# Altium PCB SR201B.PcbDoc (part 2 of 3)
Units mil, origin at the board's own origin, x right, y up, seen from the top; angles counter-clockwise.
Board outline 4100 x 3600 mil, 4 copper layers (Top Layer, Signal Layer 1, Signal Layer 2, Bottom Layer), stack 61.6 mil thick; 173 components, 61 nets, 385 pads, 260 vias.
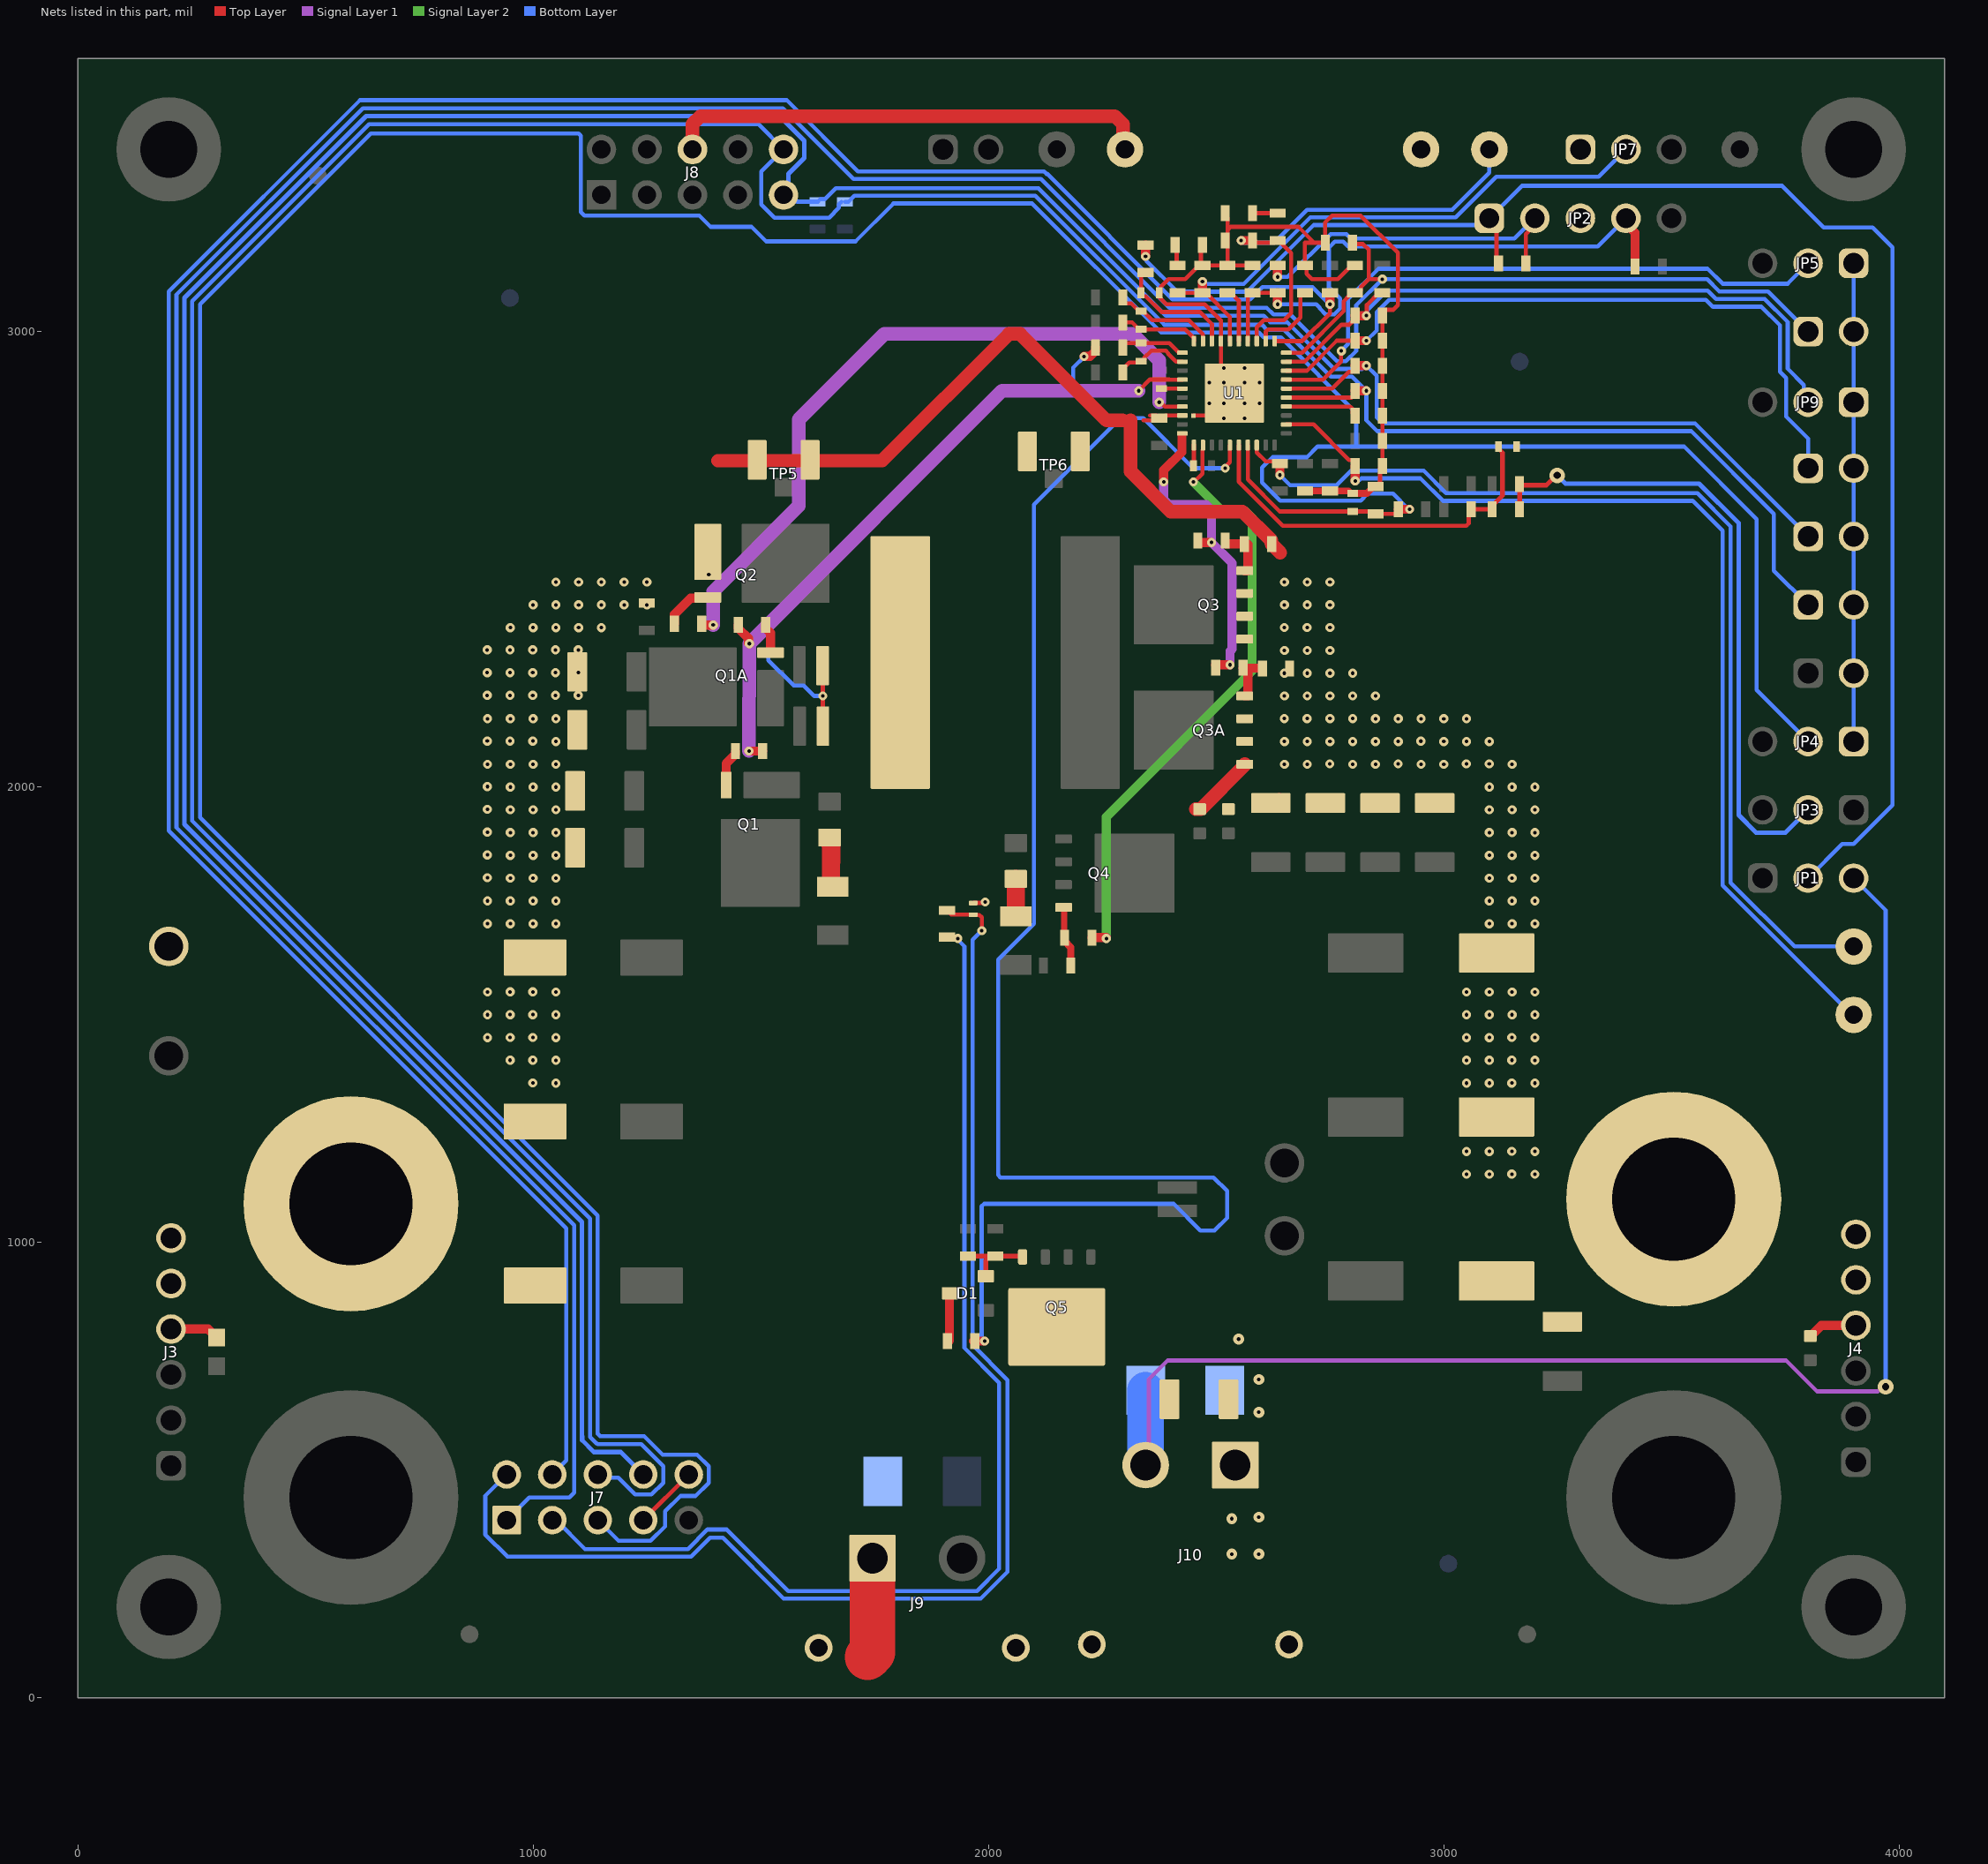
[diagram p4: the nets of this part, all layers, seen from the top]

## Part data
C1 C2 C12 C28: library part CMP-0007099-4, "CAP, CERM, 0.1 uF, 100 V, +/- 10%, X7S, AEC-Q200 Grade 1, 0603", Cap_Case=0603, Manufacturer=TDK, Supplier Part Number 1=445-6938-1-ND, TempCo=X7S, Tolerance_%=10%, Value1="0.04959 ohm", Value2=100V, ValueDisplayed=0.1uF
C3 C5 C6 C9 C14 C20 C21 C22 C40: library part CMP-0125410-1, "10 µF ±10% 100V Ceramic Capacitor X7R 1210 (3225 Metric)", Digikey Part Number=445-CGA6P1X7R2A106K250ACCT-ND, Manufacturer=TDK, Mouser Part Number=810-CGA6P1X7R2A106K2, Operating Temperature Range="-55°C to +125°C", TempCo=15%, Temperature Characteristic=X7R, Tolerance_%=10%, ValueDisplayed=10uF
C4 C7 C23: library part CMP-0097690-1, "Cap Aluminum Polymer 27uF 63V 20% Solder Cylindrical 54m Ohm 1175mA 2000 hr 125°C T/R", Digikey Part Number=399-A768KE276M1JLAE054CT-ND, Leakage Current=340uA, Manufacturer=KEMET, Mouser Part Number=80-A768KE276M1JLAE54, Operating Temperature Range="-55°C to +125°C", Tolerance_%=20%, ValueDisplayed=27uF
C8 C10 C13: library part CMP-0088837-1, "0.1µF ±10% 100V Ceramic Capacitor X7R 0603 (1608 Metric)", Digikey Part Number=490-3285-1-ND, Manufacturer=Murata, Mouser Part Number=81-GRM188R72A104KA35, Operating Temperature Range="-55°C to +125°C", TempCo=15%, Temperature Characteristic=X7R, Tolerance_%=10%, ValueDisplayed=0.1uF
C11: library part CMP-0064935-4, "CAP, CERM, 0.1 uF, 100 V,+/- 10%, X7R, AEC-Q200 Grade 1, 0603", Cap_Case=0603, Manufacturer=MuRata, Supplier Part Number 1=490-13420-1-ND, TempCo=X7R, Tolerance_%=10%, Value1=Unknown, Value2=100V, ValueDisplayed=0.1uF
C15 C16 C29: library part CMP-0006618-2, "CAP, CERM, 0.1 uF, 100 V, +/- 10%, X5R, 0402", Cap_Case=0402, Manufacturer=MuRata, Supplier Part Number 1=490-10458-1-ND, TempCo=X5R, Tolerance_%=10%, Value1=Unknown, Value2=100V, ValueDisplayed=0.1uF
C17 C18 C19: library part CMP-0128071-1, "27 µF 80 V Aluminum - Polymer Capacitors Radial, Can - SMD 38mOhm 4000 Hrs @ 125°C", Digikey Part Number=493-13785-1-ND, Leakage Current=64uA, Manufacturer=Nichicon, Mouser Part Number=647-PCR1K270MCL1GS, Operating Temperature Range="-55°C to +125°C", Tolerance_%=20%, ValueDisplayed=27uF
C24: library part CMP-0006675-2, "CAP, CERM, 0.1 uF, 50 V, +/- 20%, X7R, 0402", Cap_Case=0402, Manufacturer=MuRata, Supplier Part Number 1=490-10701-1-ND, TempCo=X7R, Tolerance_%=20%, Value1=Unknown, Value2=50V, ValueDisplayed=0.1uF
C25: library part CMP-0006445-2, "CAP, CERM, 270 pF, 50 V, +/- 5%, C0G/NP0, 0402", Cap_Case=0402, Manufacturer=MuRata, Supplier Part Number 1=490-1294-1-ND, TempCo=C0G/NP0, Tolerance_%=5%, Value1=Unknown, Value2=50V, ValueDisplayed=270pF
C26 C27: library part CMP-0092433-2, "Multi-Layer Ceramic Capacitor 22uF 10V X5R ±20% 0603 Paper T/R", Manufacturer=Murata, Operating Temperature Range="-55°C to +85°C", TempCo=15%, Temperature Characteristic=X5R, Tolerance_%=20%, ValueDisplayed=22uF
C30: library part CMP-0007537-2, "CAP, CERM, 680 pF, 100 V, +/- 5%, C0G/NP0, 0805", Cap_Case=0805, Manufacturer=AVX, Supplier Part Number 1=478-1289-1-ND, TempCo=C0G/NP0, Tolerance_%=5%, Value1="0.134 ohm", Value2=100V, ValueDisplayed=680pF
C31 C33: library part CMP-0006356-2, "CAP, CERM, 0.1 uF, 50 V, +/- 10%, X7R, AEC-Q200 Grade 1, 0402", Cap_Case=0402, Manufacturer=MuRata, Supplier Part Number 1=490-10672-1-ND, TempCo=X7R, Tolerance_%=10%, Value1=Unknown, Value2=50V, ValueDisplayed=0.1uF
C32: library part CMP-0007709-2, "CAP, CERM, 1000 pF, 100 V, +/- 5%, C0G/NP0, 0805", Cap_Case=0805, Manufacturer=Kemet, Supplier Part Number 1=399-1137-1-ND, TempCo=C0G/NP0, Tolerance_%=5%, Value1="0.025 ohm", Value2=100V, ValueDisplayed=1000pF
C34: library part CMP-0006776-4, "CAP, CERM, 220 pF, 50 V, +/- 1%, C0G/NP0, 0603", Cap_Case=0603, Manufacturer=AVX, Supplier Part Number 1=478-3719-1-ND, TempCo=C0G/NP0, Tolerance_%=1%, Value1="0.083 ohm", Value2=50V, ValueDisplayed=220pF
C35: library part CMP-0006792-4, "CAP, CERM, 56 pF, 50 V, +/- 1%, C0G/NP0, 0603", Cap_Case=0603, Manufacturer=AVX, Supplier Part Number 1=478-7922-1-ND, TempCo=C0G/NP0, Tolerance_%=1%, Value1=Unknown, Value2=50V, ValueDisplayed=56pF
C36: library part CMP-0084236-1, "CAP, CERM, 0.012 µF, 50 V,+/- 10%, X7R, AEC-Q200 Grade 1, 0603", Cap_Case=0603, Manufacturer=Kemet, TempCo=X7R, Tolerance_%=10%, Value2=50V, ValueDisplayed=0.012µF
C37: library part CMP-0086295-1, "CAP, CERM, 0.02 µF, 50 V,+/- 10%, X7R, 0603", Cap_Case=0603, Manufacturer=Yageo, TempCo=X7R, Tolerance_%=10%, Value2=50V, ValueDisplayed=0.02µF
C38: library part CMP-0006745-4, "CAP, CERM, 4700 pF, 100 V, +/- 5%, X7R, 0603", Cap_Case=0603, Manufacturer=AVX, Supplier Part Number 1=478-3710-1-ND, TempCo=X7R, Tolerance_%=5%, Value1="0.136 ohm", Value2=100V, ValueDisplayed=4700pF
C39: library part CMP-0085252-1, "CAP, CERM, 0.047 µF, 50 V,+/- 5%, X7R, 0603", Cap_Case=0603, Manufacturer=AVX, TempCo=X7R, Tolerance_%=5%, Value2=50V, ValueDisplayed=0.047µF
C41: library part CMP-0096021-1, "10 µF ±10% 100V Ceramic Capacitor X7R 1210 (3225 Metric)", Digikey Part Number=445-C3225X7R2A106K250ACCT-ND, Manufacturer=TDK, Mouser Part Number=810-C3225X7R2A106K25, Operating Temperature Range="-55°C to +125°C", TempCo=15%, Temperature Characteristic=X7R, Tolerance_%=10%, ValueDisplayed=10uF
C42: library part CMP-0006943-4, "CAP, CERM, 4700 pF, 50 V, +/- 10%, X7R, 0603", Cap_Case=0603, Manufacturer=Kemet, Supplier Part Number 1=399-1087-1-ND, TempCo=X7R, Tolerance_%=10%, Value1=Unknown, Value2=50V, ValueDisplayed=4700pF
C43 C44: library part CMP-0006959-4, "CAP, CERM, 680 pF, 50 V, +/- 5%, C0G/NP0, 0603", Cap_Case=0603, Manufacturer=Kemet, Supplier Part Number 1=399-3289-1-ND, TempCo=C0G/NP0, Tolerance_%=5%, Value1=Unknown, Value2=50V, ValueDisplayed=680pF
D1: library part CMP-0096356-1, "Diode Array 1 Pair Series Connection Schottky 70 V 200mA (DC) Surface Mount TO-236-3, SC-59, SOT-23-3", Digikey Part Number=BAS70-04-E3-18GICT-ND, Forward Current=200mA, Manufacturer=Vishay, Max Surge Forward Current=600mA, Mouser Part Number=78-BAS70-04-E3-18, Operating Temperature Range="-55°C to +125°C", Peak Reverse Current=0.02uA, ValueDisplayed=1.5pF
D2 D3: library part CMP-0005570-3, "Diode, TVS, Uni, 48 V, 77.4 Vc, SMB", Manufacturer="Diodes Inc.", Value1=600W
FID1 FID2 FID3 FID4 FID5 FID6: library part CMP-0077181-1, "Fiducial mark.  There is nothing to buy or mount.", Manufacturer=N/A
H1 H2 H3 H4: library part CMP-0003715-1, "MACHINE SCREW PAN PHILLIPS 4-40", Manufacturer="B&F Fastener Supply", Supplier Part Number 1=H703-ND
J1 J2 J5 J6: library part CMP-0055387-2, "Standard Banana Jack, Uninsulated, 15A", Manufacturer="Cinch Connectivity", Supplier Part Number 1=J147-ND
J3 J4: library part CMP-0054801-2, "Header, 2.54 mm, 6x1, Gold, TH", Color=Black, Manufacturer="Wurth Elektronik", Supplier Part Number 1=732-5319-ND
J7: library part CMP-0120964-1, "10 Position Receptacle Connector 0.100\" (2.54mm) Through Hole, Right Angle Gold", Current_A=4.7A, Digikey Part Number=SAM1215-05-ND, Manufacturer=Samtec, Mouser Part Number=200-SSW10502GDRA, Operating Temperature Range="-55°C to +125°C", Voltage_V=655V
J8: library part CMP-0055448-2, "Header (shrouded), 100mil, 5x2, High-Temperature, Gold, TH", Manufacturer=3M, Supplier Part Number 1=MHC10K-ND
J9: library part CMP-0035193-3, "Socket, DC supply, XT30, female, PIN: 2, on PCBs, THT, yellow, 15A", Current_A=15A, Manufacturer=Amass, Operating Temperature Range="-20°C to +120°C", Voltage_V=500V
J10: library part CMP-0121007-1, "Socket, DC supply, XT30, male, PIN: 2, on PCBs, THT, yellow, 15A, 500V", Current_A=15A, Manufacturer=Amass, Operating Temperature Range="-20°C to +120°C", Voltage_V=500V
J11 JP6 JP8 JP10 JP11 JP12 JP13: library part CMP-0054794-2, "Header, 2.54 mm, 2x1, Gold, TH", Color=Black, Manufacturer="Wurth Elektronik", Supplier Part Number 1=732-5315-ND
JP1 JP3 JP4 JP5 JP7 JP9: library part CMP-0054796-4, "Header, 2.54 mm, 3x1, Gold, TH", Manufacturer="Wurth Elektronik", Supplier Part Number 1=732-5316-ND
JP2: library part CMP-0084909-1, "Header, 2.54mm, 5x1, Gold, TH", Color=Black, Current_A=3A, Manufacturer="Wurth Elektronik", Voltage_V=250V
L1: library part CMP-0084625-1, "Inductor, Shielded, Metal Composite, 4.7 µH, 17 A, 0.00385 ohm, SMD", Manufacturer="Wurth Elektronik", Value1="0.00385 ohm", Value2=17A, ValueDisplayed=4.7µH
Logo3: library part CMP-0074847-1, "FCC_disclaimer"
LOGO4: library part CMP-0074769-4, Manufacturer="Texas Instruments"
Logo5: library part CMP-0074837-2, "IEC 61010-1 Hot Surface Warning", Manufacturer="Texas Instruments"
Logo6: library part CMP-0074836-1, "IEC 61010-1 Caution Warning"
LOGO7: library part CMP-0074835-1, "IEC 61010-1 High Voltage Warning"
MP1 MP2 MP3 MP4: library part CMP-0090542-1, "Hex Standoff Threaded #4-40 Nylon 0.750\" (19.05mm) 3/4\" Natural", Digikey Part Number=36-1902D-ND, Manufacturer="Keystone Electronics", Mouser Part Number=534-1902D, Operating Temperature Range=to
NT3: library part CMP-0078142-6, "Single point connection between nets.", Manufacturer=N/A
Q1 Q1A Q2: library part CMP-0128065-1, "MOSFET N-Channel 80 V 130A (Tj) 118W (Tc) Surface Mount PG-TDSON-8-34", Digikey Part Number=448-IAUCN08S7L033ATMA1CT-ND, Drain To Source Breakdown Voltage=80V, Input Capacitance At Vds="2708pF @ 40V", Manufacturer=Infineon, Mouser Part Number=726-IAUCN08S7L033ATM, Operating Temperature Range="-55°C to +175°C", Power_W=118W, Pulse Drain Current=356A, Typ Forward Diode Voltage=0.9V
Q3 Q3A Q4: library part CMP-0097724-1, "MOSFET N-Channel 60 V 23A (Ta), 135A (Tc) 3W (Ta), 100W (Tc) Surface Mount PG-TDSON-8", Digikey Part Number=448-ISC0703NLSATMA1CT-ND, Drain To Source Breakdown Voltage=60V, Input Capacitace At Vds="2700pF @ 30V", Manufacturer=Infineon, Mouser Part Number=726-ISC0703NLSATMA1, Operating Temperature Range="-55°C to +175°C", Power_W=3W, Pulse Drain Current=540A, Typ Forward Diode Voltage=0.85V
Q5: library part CMP-0000823-2, "MOSFET, N-CH, 60 V, 100 A, DNK0008A (VSON-CLIP-8)", Alternate Manufacturer=None, Manufacturer="Texas Instruments", Supplier Part Number 1=296-41076-1-ND, Value1=0.003, Value2="41 nC"
R1: library part CMP-0023198-5, "RES, 5.10 k, 1%, 0.1 W, 0603", Manufacturer=Yageo, Power_W=100mW, Supplier Part Number 1=311-5.10KHRCT-ND, TempCo="100 ppm/C", Tolerance_%=1%, Value2=0.1W, Value_Code=5k10, ValueDisplayed=5.10k
R2 R5 R7 R9 R10 R11 R15 R16 R20 R24 R27 R36 R38 R44: library part CMP-0023343-3, "RES, 0, 1%, 0.1 W, AEC-Q200 Grade 0, 0603", Manufacturer="Stackpole Electronics Inc", Power_W=100mW, Supplier Part Number 1=RMCF0603ZT0R00CT-ND, TempCo=ppm/C, Tolerance_%=1%, Value2=0.1W, Value_Code=0
R3: library part CMP-0097451-1, "10 mOhms ±1% 1W Chip Resistor Wide 0805 (2012 Metric), 0508 Automotive AEC-Q200, Current Sense Metal Foil", Manufacturer=Susumu, Operating Temperature Range="-55°C to +155°C", Power_W=1W, TempCo=50ppm/°C, Tolerance_%=1%
R4 R6: library part CMP-0090651-1, "5 mOhms ±1% 1W Chip Resistor Wide 0805 (2012 Metric), 0508 Automotive AEC-Q200, Current Sense Metal Foil", Digikey Part Number=408-1595-1-ND, Manufacturer=Susumu, Mouser Part Number=754-KRL2012EMR005FT5, Operating Temperature Range="-55°C to +155°C", Power_W=1W, TempCo=50ppm/°C, Tolerance_%=1%
R8: library part CMP-0022751-4, "RES, 10.0, 1%, 0.1 W, 0603", Manufacturer=Yageo, Power_W=100mW, Supplier Part Number 1=311-10.0HRCT-ND, TempCo="100 ppm/C", Tolerance_%=1%, Value2=0.1W, Value_Code=10R0, ValueDisplayed=10.0
R12: library part CMP-0023292-5, "RES, 82.0 k, 1%, 0.1 W, 0603", Manufacturer=Yageo, Power_W=100mW, Supplier Part Number 1=311-82.0KHRCT-ND, TempCo="100 ppm/C", Tolerance_%=1%, Value2=0.1W, Value_Code=82k0, ValueDisplayed=82.0k
R13 R14 R28: library part CMP-0025804-4, "RES, 3.0, 5%, 0.1 W, AEC-Q200 Grade 0, 0603", Manufacturer=Vishay-Dale, Power_W=100mW, Supplier Part Number 1=541-3.0GCT-ND, TempCo="200 ppm/C", Tolerance_%=5%, Value2=0.1W, Value_Code=3R00, ValueDisplayed=3.0
R17 R18: library part CMP-0022004-4, "RES, 10.0, 1%, 0.25 W, AEC-Q200 Grade 0, 0603", Manufacturer=Vishay-Dale, Power_W=250mW, Supplier Part Number 1=541-10.0SCT-ND, TempCo="100 ppm/C", Tolerance_%=1%, Value2=0.25W, Value_Code=10R0, ValueDisplayed=10.0
R19: library part CMP-0023148-5, "RES, 4.30 k, 1%, 0.1 W, 0603", Manufacturer=Yageo, Power_W=100mW, Supplier Part Number 1=311-4.30KHRCT-ND, TempCo="100 ppm/C", Tolerance_%=1%, Value2=0.1W, Value_Code=4k30, ValueDisplayed=4.30k
R21: library part CMP-0023267-5, "RES, 75.0 k, 1%, 0.1 W, 0603", Manufacturer=Yageo, Power_W=100mW, Supplier Part Number 1=311-75.0KHRCT-ND, TempCo="100 ppm/C", Tolerance_%=1%, Value2=0.1W, Value_Code=75k0, ValueDisplayed=75.0k
R22: library part CMP-0022778-5, "RES, 12.7 k, 1%, 0.1 W, 0603", Manufacturer=Yageo, Power_W=100mW, Supplier Part Number 1=311-12.7KHRCT-ND, TempCo="100 ppm/C", Tolerance_%=1%, Value2=0.1W, Value_Code=12k7, ValueDisplayed=12.7k
R23 R26: library part CMP-0018676-3, "RES, 3.0, 5%, 0.25 W, AEC-Q200 Grade 0, 1206", Manufacturer=Vishay-Dale, Power_W=250mW, Supplier Part Number 1=541-3.0ECT-ND, TempCo="200 ppm/C", Tolerance_%=5%, Value2=0.25W, Value_Code=3R00, ValueDisplayed=3.0
R25: library part CMP-0023653-3, "RES, 10.0 k, 0.1%, 0.1 W, 0603", Manufacturer="Yageo America", Power_W=100mW, TempCo="25 ppm/C", Tolerance_%=0.1%, Value2=0.1W, Value_Code=10k0, ValueDisplayed=10.0k
R29: library part CMP-0022599-4, "RES, 7.15 k, 1%, 0.1 W, AEC-Q200 Grade 0, 0603", Manufacturer=Vishay-Dale, Power_W=100mW, Supplier Part Number 1=541-7.15KHCT-ND, TempCo="100 ppm/C", Tolerance_%=1%, Value2=0.1W, Value_Code=7k15, ValueDisplayed=7.15k
R30: library part CMP-0022410-4, "RES, 40.2 k, 1%, 0.1 W, AEC-Q200 Grade 0, 0603", Manufacturer=Vishay-Dale, Power_W=100mW, Supplier Part Number 1=541-40.2KHCT-ND, TempCo="100 ppm/C", Tolerance_%=1%, Value2=0.1W, Value_Code=40k2, ValueDisplayed=40.2k
R31: library part CMP-0023330-5, "RES, 97.6 k, 1%, 0.1 W, 0603", Manufacturer=Yageo, Power_W=100mW, Supplier Part Number 1=311-97.6KHRCT-ND, TempCo="100 ppm/C", Tolerance_%=1%, Value2=0.1W, Value_Code=97k6, ValueDisplayed=97.6k
R32 R33: library part CMP-0025807-4, "RES, 3.9, 5%, 0.1 W, AEC-Q200 Grade 0, 0603", Manufacturer=Vishay-Dale, Power_W=100mW, Supplier Part Number 1=541-3.9GCT-ND, TempCo="200 ppm/C", Tolerance_%=5%, Value2=0.1W, Value_Code=3R90, ValueDisplayed=3.9
R34: library part CMP-0022204-4, "RES, 20.0 k, 1%, 0.1 W, AEC-Q200 Grade 0, 0603", Manufacturer=Vishay-Dale, Power_W=100mW, Supplier Part Number 1=541-20.0KHCT-ND, TempCo="100 ppm/C", Tolerance_%=1%, Value2=0.1W, Value_Code=20k0, ValueDisplayed=20.0k
R35: library part CMP-0023068-4, "RES, 390 k, 1%, 0.1 W, 0603", Manufacturer=Yageo, Power_W=100mW, Supplier Part Number 1=311-390KHRCT-ND, TempCo="100 ppm/C", Tolerance_%=1%, Value2=0.1W, Value_Code=390k
R37: library part CMP-0022205-4, "RES, 20.5 k, 1%, 0.1 W, AEC-Q200 Grade 0, 0603", Manufacturer=Vishay-Dale, Power_W=100mW, Supplier Part Number 1=541-20.5KHCT-ND, TempCo="100 ppm/C", Tolerance_%=1%, Value2=0.1W, Value_Code=20k5, ValueDisplayed=20.5k
R39 R40: library part CMP-0023000-5, "RES, 2.00 k, 1%, 0.1 W, 0603", Manufacturer=Yageo, Power_W=100mW, Supplier Part Number 1=311-2.00KHRCT-ND, TempCo="100 ppm/C", Tolerance_%=1%, Value2=0.1W, Value_Code=2k00, ValueDisplayed=2.00k
R41: library part CMP-0022381-4, "RES, 3.83 k, 1%, 0.1 W, AEC-Q200 Grade 0, 0603", Manufacturer=Vishay-Dale, Power_W=100mW, Supplier Part Number 1=541-3.83KHCT-ND, TempCo="100 ppm/C", Tolerance_%=1%, Value2=0.1W, Value_Code=3k83, ValueDisplayed=3.83k
R42: library part CMP-0023307-5, "RES, 8.25 k, 1%, 0.1 W, 0603", Manufacturer=Yageo, Power_W=100mW, Supplier Part Number 1=311-8.25KHRCT-ND, TempCo="100 ppm/C", Tolerance_%=1%, Value2=0.1W, Value_Code=8k25, ValueDisplayed=8.25k
R43: library part CMP-0025686-1, "RES, 10.0 k, 0.1%, 0.1 W, AEC-Q200 Grade 1, 0603", Manufacturer=Vishay-Dale, Power_W=100mW, Supplier Part Number 1=TNP10.0KAACT-ND, TempCo="25 ppm/C", Tolerance_%=0.1%, Value2=0.1W, Value_Code=10k0, ValueDisplayed=10.0k
RT1: library part CMP-0123214-2, "±1% tolerance 10kΩ linear thermistor available in 0402 and 0603 package options 2-X1SON -40 to 125", Digikey Part Number=296-TMP6131DECRCT-ND, Manufacturer="Texas Instruments", Mouser Part Number=595-TMP6131DECR, Operating Temperature Range="-40°C to +125°C", Tolerance_%=1%
SH-JP1 SH-JP2 SH-JP3 SH-JP4 SH-JP5 SH-JP6 SH-JP7 SH-JP8 SH-JP9 SH-JP10 SH-JP11 SH-JP12: library part CMP-0078738-1, "Single Operation 2.54mm Pitch Open Top Jumper Socket", Manufacturer=Harwin, Supplier Part Number 1=952-2881-ND
TP1 TP2: library part CMP-0055150-2, "Test Point, Multipurpose, Orange, TH", Color=Orange, Manufacturer="Keystone Electronics", Supplier Part Number 1=36-5013-ND
TP3: library part CMP-0055147-2, "Test Point, Multipurpose, Red, TH", Color=Red, Manufacturer="Keystone Electronics", Supplier Part Number 1=36-5010-ND
TP4 TP7: library part CMP-0055138-2, "Test Point, Miniature, Black, TH", Color=Black, Manufacturer="Keystone Electronics", Supplier Part Number 1=36-5001-ND
TP5 TP6: library part CMP-0124001-1, "U.FL (UMCC), I-PEX MHFI Connector Receptacle, Male Pin 50 Ohms Surface Mount Solder", Dielectric Material="Liquid Crystal Polymer", Digikey Part Number=SAM10680-ND, Frequency_Fixed=6GHz, Manufacturer=Samtec, Operating Temperature Range="-40°C to +90°C", Voltage_V=60V
TP8: library part CMP-0055148-2, "Test Point, Multipurpose, Black, TH", Color=Black, Manufacturer="Keystone Electronics", Supplier Part Number 1=36-5011-ND
TP9 TP10 TP11 TP12 TP13: library part CMP-0055141-2, "Test Point, Miniature, Yellow, TH", Color=Yellow, Manufacturer="Keystone Electronics", Supplier Part Number 1=36-5004-ND
U1: library part CMP-0127274-2, "80V VIN4 Switch Buck-Boost Controller with I2C", Manufacturer="Texas Instruments", Operating Temperature Range=to
ZZ2: library part CMP-0077236-1
ZZ3: library part CMP-0077237-1
ZZ4: library part CMP-0077238-1

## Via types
v1: diameter 20, hole 8, Top Layer to Bottom Layer, tented both sides, 239 vias
v2: diameter 19.68, hole 7.87, Top Layer to Bottom Layer, tented both sides, 12 vias
v3: diameter 24, hole 8, Top Layer to Bottom Layer, tented both sides, 7 vias
v4: diameter 34, hole 16, Top Layer to Bottom Layer, tented both sides, 2 vias

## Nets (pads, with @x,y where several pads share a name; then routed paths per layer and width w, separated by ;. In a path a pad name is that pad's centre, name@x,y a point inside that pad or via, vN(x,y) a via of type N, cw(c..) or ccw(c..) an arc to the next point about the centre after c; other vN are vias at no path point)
ADDR: JP9.2 R36.2 R38.1 U1.9 | length 1467.9
  Top Layer w9: U1.9@2654.17,2933.9 2654.59,2934.32 2694.32,2934.32 2775,3015 2792.5,3015 2805,3027.5 R38.1@2805,3035 ; v1(2830,3035) 2831,3036 2831,3058.5 2857.5,3085 R36.2@2865,3085
  Top Layer w20: R38.1@2805,3035 v1(2830,3035)
  Bottom Layer w9: v1(2830,3035) 2832.1,3037.1 2832.1,3047.1 2875,3090 3579.49,3090 3598.09,3071.4 3704.74,3071.4 3755.15,3020.99 3755.15,2918.48 3790.8,2882.83 3790.8,2854.2 JP9.2@3800,2845
AGND: C15.1 C16.2 C26.1 C28.1 C29.2 C34.2 C35.2 C36.2 C37.2 C38.2 C39.2 J8.6 J11.2 JP2.3 JP4.1 JP5.1 JP6.2 JP7.1 JP8.2 JP9.1 JP10.2 JP11.2 JP13.1 NT3.2 R10.1 R19.1 R22.1 R24.1 R27.1 R30.1 R31.1 R37.1 R38.2 R41.1 R42.1 TP4.1 TP7.1 U1.17 U1.41 | length 4306
  Top Layer w9: NT3.2@2450.26,2815.5 2490.5,2815.5 v2(2517.36,2842.36) U1.41@2540,2865 ; C39.2@2466.57,3190 2466.57,3148.43 C38.2@2470,3145 ; v2(2517.36,2920.12) 2515.82,2920.12 2510.47,2925.46 U1.17@2510.47,2979.17 2510.47,3024.53 2475,3060 2390.5,3060 2372.5,3078 2378,3083.5 2378,3097.69 2395.32,3115 2432.5,3115 2462.5,3145 2466.57,3145 C38.2@2470,3145 ; C36.2@2525,3250 2525,3222.5 ; R19.1@2580,3145 R10.1@2525,3145 ; R30.1@2805,3145 2797.5,3145 2767.5,3115 2710.56,3115 2698.79,3126.77 2698.79,3141.21 R31.1@2695,3145 2695,3195 2715.67,3195 ; R22.1@2850,2660 R22.1@2854.5,2664.5 ; R22.1@2860,2664.5 R22.1@2854.5,2664.5 ; R22.1@2860,2665.5 R22.1@2860,2668.31 ; C38.2@2470,3145 R10.1@2525,3145 ; R10.1@2525,3145 2525,3195 2525,3222.5 ; 2525,3222.5 2532.5,3230 2680.67,3230 2715.67,3195 ; 2715.67,3195 C35.2@2739.68,3195 2739.68,3239.68 2755,3255 2817.21,3255 2899.07,3173.14 2899.07,3057.71 2889.37,3048 2870.5,3048 2865,3042.5 R38.2@2865,3035 R37.1@2865,2980 R42.1@2865,2925 R41.1@2865,2870 R27.1@2865,2815 R24.1@2865,2760 C37.2@2865,2705 2860,2700 R22.1@2860,2668.31 ; R22.1@2854.5,2664.5 2858.31,2668.31 R22.1@2860,2668.31
  Top Layer w15: C28.1@2695,2650 C26.1@2750,2650 2790.5,2650 2795.5,2645 2831.21,2645 2840,2653.79 2840,2657.5 2842.5,2660 R22.1@2850,2660
  Top Layer w30: J8.6@1350,3400 1350,3455.44 1367.57,3473.01 2277.65,3473.01 2295.23,3455.44 2295.23,3404.77 TP7.1@2300,3400
  Bottom Layer w9: JP13.1@3900,2100 JP6.2@3900,2250 JP10.2@3900,2400 JP11.2@3900,2550 JP8.2@3900,2700 JP9.1@3900,2845 J11.2@3900,3000 JP5.1@3900,3150
  other v2: 2517.36,2809.88 2562.64,2809.88 2484.88,2842.36 2562.64,2842.36 2595.12,2842.36 2484.88,2887.64 2517.36,2887.64 2562.64,2887.64 2595.12,2887.64 2562.64,2920.12
BIAS: JP3.2 R5.2 R11.2 | length 1416
  Top Layer w10: R5.2@3166.69,2609.65 3166.69,2662.17 3167.19,2662.66 3225.38,2662.66 3247.12,2684.4 v4(3248.9,2684.4)
  Bottom Layer w10: v4(3248.9,2684.4) 3267.25,2666.05 3560.63,2666.05 3647.37,2579.31 3647.37,1938.49 3685.86,1900 3750,1900 JP3.2@3800,1950
BIAS36: C15.2 R5.1 R7.1 U1.36 | length 861.3
  Top Layer w9: U1.36@2549.84,2750.83 2549.84,2670.16 2646.32,2573.68 3049.46,2573.68 3054.73,2578.96 3054.73,2610 R7.1@3060,2610
  Top Layer w10: R7.1@3060,2610 3060.35,2609.65 R5.1@3106,2609.65 3106,2617.15 3128.87,2640.03 3128.87,2734.25 3120,2743.13 C15.2@3120,2747.63
CDC: C35.1 J7.1 J11.1 R30.2 U1.10 | length 7729.3
  Top Layer w9: U1.10@2654.17,2953.58 2688.58,2953.58 2780,3045 2780,3066.3 2792,3078.3 2792,3079.5 2797.5,3085 R30.2@2805,3085 2812.5,3085 2818,3090.5 2818,3098 2835,3115 ; C35.1@2799.68,3195 2802.6,3192.09 2822.91,3192.09 2835,3180 2835,3115 ; v1(2865,3115) 2835,3115
  Bottom Layer w9: J7.1@942.09,390.59 991.5,440 1079.34,440 1090,450.66 1090,525.3 1090,1037.75 216.87,1910.87 216.87,3081.02 626.24,3490.38 1548.33,3490.38 1703.71,3335 2115,3335 2397.63,3052.37 2610.98,3052.37 2625.73,3037.63 2663.12,3037.63 2765.75,2935 2784.95,2935 2807.63,2957.67 2807.63,3057.63 v1(2865,3115) ; v1@2865.77,3115 3578.35,3115 3605.08,3088.27 3711.73,3088.27 J11.1@3800,3000
CFG2: JP8.1 R37.2 U1.8 | length 1535
  Top Layer w9: U1.8@2654.17,2914.21 2699.21,2914.21 2765,2980 R37.2@2805,2980
  Top Layer w20: R37.2@2805,2980 v1(2830,2980)
  Bottom Layer w9: v1(2830,2980) 2852.37,3002.37 2852.37,3042.69 2879.68,3070 3575.63,3070 3591.1,3054.52 3697.75,3054.52 3738.27,3014 3738.27,2911.49 3751.57,2898.19 3751.57,2813.43 3800,2765 JP8.1@3800,2700
COMP: C34.1 R29.2 TP12.1 U1.13 | length 1025.3
  Top Layer w9: C34.1@2585,3195 2628,3195 2635,3202 2665,3172 2665,3040.85 2649.15,3025 2605,3025 2589.21,3009.21 U1.13@2589.21,2979.17
  Top Layer w20: v1(2555,3200) C34.1@2580,3200
  Bottom Layer w9: v1@2560,3195 2627.27,3195 2699.89,3267.62 3018.75,3267.62 3100,3348.86 TP12.1@3100,3400
CSA/SW1: C25.2 R17.1 U1.22 | length 168.5
  Top Layer w9: R17.1@2295,2910 2295,2917.5 2309.5,2932 2332,2932 C25.2@2335,2935 2339.5,2935 2342.5,2938 2342.5,2942.5 2358.13,2958.13 2389.41,2958.13 2394.68,2952.85 2394.68,2951.65 2412.01,2934.32 2425.41,2934.32 U1.22@2425.83,2933.9
CSB: C25.1 R18.1 U1.21 | length 146.5
  Top Layer w9: R18.1@2295,2965 2295,2969.5 2300.5,2975 C25.1@2335,2975 2397.52,2975 2418.94,2953.58 U1.21@2425.83,2953.58
DRV1: C2.1 U1.35 | length 3581.3
  Top Layer w9: v1(2520,2700) 2520,2702.98 2530.16,2713.13 U1.35@2530.16,2750.83
  Top Layer w20: C2.1@1966.58,783.46 v1(1991.58,783.46)
  Bottom Layer w9: v1(1991.58,783.46) 1991.58,786.44 1985,793.02 1985,1079.73 1990.27,1085 2406.9,1085 2465.33,1026.57 2496.67,1026.57 2498.1,1028 2524.01,1053.9 2524.01,1113.39 2494.48,1142.92 2026.39,1142.92 2021.12,1148.19 2021.12,1621.12 2100,1700 2100,2620 2290,2810 2340,2810 2450,2700 v1(2520,2700)
DTRK: R27.2 U1.4 | length 165
  Top Layer w9: U1.4@2654.17,2835.47 2794.23,2835.47 2799.5,2830.2 2799.5,2820.5 R27.2@2805,2815
EN/UVLO: C29.1 J7.5 JP4.2 JP13.2 R21.1 R22.2 U1.37 | length 9234.6
  Top Layer w9: U1.37@2569.53,2750.83 2569.53,2675.47 2640,2605 C29.1@2800,2605 R22.2@2842.5,2605 ; R22.2@2850,2600 2894.5,2600 2900,2605.5 R21.1@2900,2610
  Top Layer w20: R21.1@2900,2610 v1(2925,2610)
  Bottom Layer w9: J7.5@1142.09,390.59 1187.68,345 1258.26,345 1290,376.74 1290,410 1323.5,443.5 1356.76,443.5 1385.76,472.5 1385.76,508.68 1360.18,534.26 1284.6,534.26 1243.86,575 1147.15,575 1141.87,580.27 1141.87,1059.49 268.5,1932.87 268.5,3059.63 643.86,3435 1099.73,3435 1105,3429.73 1105,3262.54 1112.54,3255 1365,3255 1390,3230 1480,3230 1511.99,3198.01 1708.01,3198.01 1791.25,3281.25 2096.02,3281.25 2379.41,2997.86 2593.9,2997.86 2604.76,2987 2642.15,2987 2807.55,2821.59 2807.55,2747.63 ; v1(2925,2610) 2922.35,2610 2888.34,2644.02 2832.71,2644.02 2817.57,2628.88 2640.62,2628.88 2600.75,2668.74 2600.75,2701.26 2623.74,2724.25 2699.25,2724.25 2722.63,2747.63 2807.55,2747.63 ; JP13.2@3800,2100 3686.87,2213.13 3686.87,2588.24 3527.49,2747.63 2807.55,2747.63
FB: JP2.4 R2.1 R12.1 R19.2 U1.14 | length 1291.7
  Top Layer w9: U1.14@2569.53,2979.17 2569.53,3079.5 2575.03,3085 R19.2@2580,3085 R12.1@2635,3085
  Top Layer w20: v1(2635,3060) R12.1@2635,3085 ; JP2.4@3400,3248.86 3400,3236.69 3420,3216.69 R2.1@3420,3143
  Bottom Layer w9: v1(2635,3060) 2720,3060 2727.63,3052.37 2727.63,3050.73 2740.73,3037.63 2759.27,3037.63 2772.37,3050.73 2772.37,3072.63 2747.63,3097.37 2747.63,3184.27 2760.73,3197.37 2779.27,3197.37 2789.51,3187.13 3338.27,3187.13 JP2.4@3400,3248.86
GND: C3.1 C4.1 C5.1 C6.1 C7.1 C8.1 C9.1 C10.1 C11.2 C12.2 C13.1 C14.1 C17.1 C18.1 C19.1 C20.1 C21.1 C22.1 C23.1 C27.1 C40.1 C41.1 C43.2 C44.2 D2.2 D3.2 J3.4 J3.5 J3.6 J4.4 J4.5 J4.6 J5.1 J6.1 J7.7 J7.10 J9.1 J9.3 J9.4 J10.1 J10.3 J10.4 NT3.1 Q2.1-2-3 Q3.1 Q3.2 Q3.3 Q3A.1 Q3A.2 Q3A.3 RT1.1 TP5.2 TP5.3 TP6.2 TP6.3 TP8.1 U1.28 | length 2508.5
  Top Layer w9: RT1.1@1966.58,1745.28 1967,1745.7 1990.84,1745.7 v1(1992.79,1747.65) v1@1992.5,1747.94 ; 2295,2805 2312.13,2805 ; 2340.5,2805.5 2370.5,2805.5 C27.1@2375,2810 ; 2355,2815.5 2369.5,2815.5 C27.1@2375,2810 ; U1.28@2425.83,2815.79 2388.29,2815.79 2382.5,2810 C27.1@2375,2810 ; U1.28@2429.76,2816 NT3.1@2430.26,2815.5
  Top Layer w10: J7.7@1242.09,390.59 J7.10@1342.09,490.59
  Top Layer w20: J3.4@205,810 286.5,810 295.31,801.18 296.3,801.18 305,792.48 C11.2@305,791.5 ; C8.1@3805,794.65 3805.98,794.65 3829.41,818.07 J4.4@3905,818.07
  Top Layer w30: 1405.69,2716.5 1766.5,2716.5 2044.88,2994.88 2069.73,2994.88 2259.61,2805 2295,2805 ; 2312.13,2805 2312.13,2692.87 2400,2605 2557.7,2605 2621.1,2541.6 C43.2@2621.1,2535.53 ; C10.1@2455,1951.58 2466.32,1951.58 2562.8,2048.05 Q3A.1@2562.8,2050 ; C21.1@2620,1964.96 2632.3,1964.96 C21.1@2638.95,1971.61 ; C43.2@2622.17,2533.03 2640.62,2514.58
  Top Layer w100: 1735,90 1745.24,100.24 J9.1@1745.24,306.98
  other v1: 3050,1150 3100,1150 3149.41,1150.22 3200,1150 3050,1200 3100,1200 3149.41,1200.22 3200,1200 999.44,1350.36 1050,1350 3050,1350 3100,1350 3149.41,1350.22 3200,1350 949.55,1400.36 999.44,1400.36 1050,1400 3050,1400 3100,1400 3149.41,1400.22 3200,1400 900,1450 949.55,1450.36 999.44,1450.36 1050,1450 3050,1450 3100,1450 3149.41,1450.22 3200,1450 900,1500 949.55,1500.36 999.44,1500.36 1050,1500 3050,1500 3100,1500 3150,1500 3200,1500 900,1550 949.55,1550.36 999.44,1550.36 1050,1550 3050,1550 3100,1550 3150,1550 3200,1550 900,1700 950,1700 1000,1700 1050,1700 3100,1700 3150,1700 3200,1700 900,1750 950,1750 1000,1750 1050,1750 3100,1750 3150,1750 3200,1750 950,1800 1000,1800 1050,1800 3100,1800 3150,1800 3200,1800 899.66,1801.02 950,1850 1000,1850 1050,1850 3100,1850 3150,1850 3200,1850 899.66,1851.02 950,1900 1000,1900 1050,1900 3100,1900 3150,1900 3200,1900 899.66,1901.02 950,1950 1000,1950 1050,1950 3100,1950 3150,1950 3200,1950 899.66,1951.02 950,2000 1000,2000 1050,2000 3100,2000 3150,2000 3200,2000 899.66,2001.02 900,2050 950,2050 1000,2050 1050,2050 2650,2050 2700,2050 2800,2050 2850,2050 2950,2050 3000,2050 3150,2050 2749.66,2050.82 2899.66,2050.82 3049.66,2050.82 3099.66,2050.82 1050,2100 2650,2100 2700,2100 2750,2100 2800,2100 2850,2100 2900,2100 3000,2100 3050,2100 3100,2100 899.46,2101.03 949.46,2101.03 999.46,2101.03 2949.66,2100.82 900,2150 950,2150 1000,2150 1050,2150 2649.9,2150.36 2699.9,2150.36 2749.9,2150.36 2799.9,2150.36 2850,2150 2900,2150 2950,2150 3000,2150 3050,2150 2650,2200 2700,2200 2750,2200 2800,2200 2850,2200 899.22,2201.35 949.22,2201.35 999.22,2201.35 1049.22,2201.35 1099.22,2201.35 2650,2250 2700,2250 2750,2250 2800,2250 899.22,2251.24 949.22,2251.24 999.22,2251.24 1049.22,2251.24 1099.22,2251.24 2650,2300 2700,2300 2750,2300 899.22,2301.13 949.22,2301.13 999.22,2301.13 1049.22,2301.13 1099.22,2301.13 950,2350 1000,2350 1050,2350 1100,2350 1150,2350 2649.9,2350.36 2699.9,2350.36 2749.9,2350.36 1000,2400 1050,2400 1100,2400 1150,2400 1200,2400 1250,2400 2650,2400 2700,2400 2750,2400 1050,2450 1100,2450 1150,2450 1200,2450 1250,2450 2650,2450 2700,2450 2750,2450 1385.8,2466.37
  other v3: 2534.35,315.87 2593.73,315.87 2534.35,393.59 2593.73,397.01 2593.73,627.5 2593.73,699.42 2549.45,787.91
HB1: C31.2 U1.25 | length 45.9
  Top Layer w9: C31.2@2380,2875 2380.08,2874.92 2425.75,2874.92 U1.25@2425.83,2874.84
HB2: C33.2 U1.31 | length 46.4
  Top Layer w10: C33.2@2450,2705 2451.34,2706.34 2451.34,2750.75 U1.31@2451.42,2750.83
HO1: R13.1 R14.1 U1.24 | length 1507.9
  Top Layer w9: v1(2330,2870) 2354.87,2894.87 2397.13,2894.87 2397.47,2894.53 U1.24@2425.83,2894.53
  Top Layer w20: R14.1@1450.99,2355.87 1450.99,2348.37 1473.09,2326.28 1473.09,2316.91 v1(1475,2315) ; v1(1474.31,2079.08) R13.1@1504.31,2079.08
  Signal Layer 1 w30: v1(1474.31,2079.08) v1(1475,2315) 2030,2870 v1(2330,2870)
HO1_G: Q1.4 R13.2 | length 83.1
  Top Layer w20: Q1.4@1424.01,2004.4 1424.01,2051.28 1444.31,2071.58 R13.2@1444.31,2079.08
HO2: R20.1 U1.32 | length 1340.3
  Top Layer w9: v1(2450,2670) 2452,2670 2469.87,2687.87 2469.87,2740.38 2470.68,2741.19 2470.68,2750.41 U1.32@2471.1,2750.83
  Top Layer w20: R20.1@2227.2,1669.42 v1@2258.92,1669.42
  Signal Layer 2 w20: v1(2258.92,1667.45) 2258.92,1934.4 2579.01,2254.48 2579.01,2590.99 2565,2605 2515,2605 v1(2450,2670)
HO2_G: C42.2 Q4.4 R20.2 | length 134.4
  Top Layer w10: R20.2@2167.2,1661.92 R20.2@2167.2,1669.42
  Top Layer w13: Q4.4@2165.12,1735.87 2166.16,1734.83 2166.16,1670.46 R20.2@2167.2,1669.42
  Top Layer w16: R20.2@2167.2,1661.92 2180.85,1648.27 C42.2@2180.85,1608.03
ILIMCOMP: C38.1 JP7.2 R34.2 U1.16 | length 1269.8
  Top Layer w9: R34.2@2415,3085 C38.1@2470,3085 2477.5,3085 2530.16,3032.34 U1.16@2530.16,2979.17
  Top Layer w20: C38.1@2470,3085 v1(2470,3110)
  Bottom Layer w9: v1(2470,3110) 2472.98,3110 2478.48,3104.5 2560.64,3104.5 2706.88,3250.74 3025.74,3250.74 3115,3340 3340,3340 JP7.2@3400,3400
ISNSN: C24.1 R16.1 U1.19 | length 228.8
  Top Layer w9: R16.1@2295,3075 2295,3067.5 2300.5,3062 2313.5,3062 2330.5,3045 C24.1@2335,3045 2339.5,3045 2359.5,3025 2440,3025 2470.68,2994.32 2470.68,2979.59 U1.19@2471.1,2979.17
ISNSP: C24.2 R15.1 U1.20 | length 177.4
  Top Layer w9: R15.1@2295,3020 2315.5,3020 2330.5,3005 C24.2@2335,3005 2432.48,3005 2451,2986.48 2451,2985 2451.42,2984.58 U1.20@2451.42,2979.17
LO1: R28.2 U1.27 | length 1597
  Top Layer w9: v1(2375,2845) 2377.98,2845 2387.5,2835.47 U1.27@2425.83,2835.47
  Top Layer w20: R28.2@1370.28,2358.56 1370.28,2355.87 v1(1395.64,2355.87)
  Signal Layer 1 w30: v1(1395.64,2355.87) 1395.64,2429.72 1583.53,2617.62 1583.53,2807.11 1771.42,2995 2316.65,2995 2375,2936.65 v1(2375,2845)
LO1_G: Q2.4 R28.1 | length 109.5
  Top Layer w20: R28.1@1310.28,2358.56 1310.28,2379.07 1345.77,2414.56 1382.02,2414.56 Q2.4@1383.83,2416.37
LO2: R32.1 R33.1 U1.30 | length 691.6
  Top Layer w20: v1(2385,2670) 2385,2695.58 2425,2735.58 2425,2770 ; R32.1@2461.4,2535 2461.4,2536.97 v1(2489.82,2536.97) ; R33.1@2499.23,2268.41 v1(2530.67,2268.41)
  Signal Layer 1 w20: v1(2385,2670) 2385,2631.72 2396.72,2620 2478.11,2620 2489.82,2608.28 v1(2489.82,2536.97) 2535,2491.79 2535,2302.74 2530.67,2298.41 v1(2530.67,2268.41)
LO2_G: C43.1 Q3.4 R32.2 | length 107.9
  Top Layer w20: R32.2@2521.4,2535 2521.4,2534.02 2561.81,2534.02 C43.1@2562.8,2533.03 ; Q3.4@2562.8,2475 2569.84,2475 2570,2475.16 C43.1@2570,2533.03
MODE: JP5.2 U1.7 | length 1350.1
  Top Layer w9: U1.7@2654.17,2894.53 2734.53,2894.53 2774,2934 2774,2956.5 v1(2775,2957.5)
  Bottom Layer w9: v1(2775,2957.5) 2790,2972.5 2790,3071.64 2856.31,3137.96 3579.26,3137.96 3612.07,3105.15 3755.15,3105.15 JP5.2@3800,3150
NetC1_1: C1.1 D1.2 Q5.4 R1.1 | length 173.7
  Top Layer w10: C1.1@1955,970 2007.5,970 2073.43,970 Q5.4@2075,968.43 ; D1.2@1994.37,925.87 1994.37,960.33 R1.1@2007.5,973.46
NetC2_2: C2.2 D1.3 | length 105.9
  Top Layer w20: C2.2@1913.42,783.46 1914.53,784.57 1914.53,887.36 D1.3@1915.63,888.46
NetC16_1: C16.1 R9.1 U1.18 | length 272.9
  Top Layer w9: C16.1@2335,3085 2335,3080.5 2338,3077.5 2345.5,3077.5 2379.88,3043.13 2464.22,3043.13 2490.79,3016.56 U1.18@2490.79,2979.17 ; C16.1@2335,3088 2335,3124.5 2340.5,3130 R9.1@2345,3130
NetC30_1: C30.1 R23.1 | length 94.6
  Top Layer w40: C30.1@1651.18,1877.08 1654.46,1877.08 1654.78,1876.76 R23.1@1654.46,1785.87
NetC32_1: C32.1 R26.1 | length 78.3
  Top Layer w40: R26.1@2060,1719.96 C32.1@2060,1798.22
NetC36_1: C36.1 R29.1 | length 55
  Top Layer w9: C36.1@2580,3260 R29.1@2635,3260
NetC39_1: C39.1 R34.1 | length 45.7
  Top Layer w9: C39.1@2413.43,3190 2413.43,3146.57 R34.1@2415,3145
NetC44_1: C44.1 Q3A.4 R33.2 | length 108.3
  Top Layer w20: R33.2@2559.23,2260.98 C44.1@2599.02,2260.98 ; Q3A.4@2562.8,2200 2569.84,2200 2570,2200.16 2570,2260 R33.2@2569.02,2260.98
NetJP1_2: JP1.2 JP2.1 R8.2 R9.2 | length 3437.2
  Top Layer w9: JP2.1@3100,3248.86 3115.87,3232.99 3115.87,3154.13 R8.2@3120,3150
  Top Layer w20: v1(2345,3165) R9.2@2345,3190
  Bottom Layer w9: v1(2345,3165) 2347.1,3162.9 2347.1,3155.12 2414.6,3087.63 2567.63,3087.63 2713.87,3233.87 3085.01,3233.87 3171.14,3320 3742.68,3320 3834.08,3228.6 3941.4,3228.6 3985,3185 3985,1960 3900,1875 3875,1875 JP1.2@3800,1800
NetJP2_2: JP2.2 R8.1 R12.2 | length 759
  Top Layer w9: R8.1@3180,3150 3180,3213.72 3200,3233.72 JP2.2@3200,3248.86
  Top Layer w20: v1(2635,3120) R12.2@2635,3145
  Bottom Layer w9: v1(2635,3120) 2657.32,3120 2751.57,3214.25 2786.26,3214.25 2796.5,3204 3155.15,3204 JP2.2@3200,3248.86
NetL1_1: L1.1 R4.1 R6.1 R18.2 | length 1420.5
  Top Layer w9: L1.1@1756.42,2213.46 1796.02,2253.06 L1.1@1801.42,2247.67
  Top Layer w10: R6.1@1635.89,2266.3 1636.18,2266.01 v1(1636.18,2200) 1636.18,2133.99 R4.1@1636.47,2133.7
  Top Layer w20: v1(2210,2945) 2210.37,2945.37 2222.87,2945.37 2235,2957.5 R18.2@2235,2965
  Bottom Layer w9: v1(1636.18,2200) 1617.35,2200 1594.47,2222.87 1572.44,2222.87 1516.87,2278.44 1516.87,2344.98 2034.08,2862.19 2172.19,2862.19 2185.99,2875.99 2185.99,2920.99 v1(2210,2945)
NetQ1A_4: Q1A.4 R14.2 | length 65.1
  Top Layer w20: R14.2@1510.99,2355.87 1510.99,2348.37 1521.46,2337.91 Q1A.4@1521.46,2295.07
NetR10_2: R10.2 U1.15 | length 120.5
  Top Layer w9: R10.2@2525,3085 2532.5,3085 2549.84,3067.66
  Top Layer w10: U1.15@2549.84,2979.17 2549.84,3067.66
nFLT: J7.4 R25.1 U1.11 | length 6120.4
  Top Layer w9: U1.11@2628.58,2979.17 2689.17,2979.17 2750,3040 v1(2750,3060) R25.1@2750,3085
  Top Layer w20: v1(2750,3060) R25.1@2750,3085
  Bottom Layer w9: J7.4@1042.09,490.59 1073.13,521.63 1073.13,532.29 1073.13,1030.76 200,1903.88 200,3088 620.01,3508.01 1556.99,3508.01 1713.13,3351.87 2121.99,3351.87 2127.49,3346.38 2128.62,3346.38 2404.25,3070.75 2574.62,3070.75 2601.49,3097.63 2711.6,3097.63 2749.23,3060 v1(2750,3060)
nRST: R35.1 TP11.1 U1.38 | length 2275.6
  Top Layer w9: U1.38@2589.21,2750.83 2589.46,2750.58 2589.46,2734.4 2609,2714.86 2635.14,2714.86 R35.1@2640,2710
  Top Layer w20: v1(2640,2685) R35.1@2640,2710
  Bottom Layer w9: v1(2640,2685) 2662.37,2662.63 2764.17,2662.63 2796.19,2694.64 2955.87,2694.64 3005.19,2645.31 3556.8,2645.31 3630,2572.11 3630,1790 3770,1650 TP11.1@3900,1650
PDCTRL_GOOD: J7.3 R43.1 | length 2548.2
  Top Layer w9: R43.1@1909.14,1670.47 1910.65,1668.96 1931.25,1668.96 v1(1932.76,1667.45)
  Bottom Layer w9: J7.3@1042.09,390.59 1050.39,390.59 1114.1,326.87 1340.13,326.87 1383.26,370 1425,370 1560,235 1975,235 2023.69,283.69 2023.69,692.33 1947.3,768.72 1947.3,1649.94 1932.76,1664.48 v1(1932.76,1667.45)
PPHV: C41.2 D3.1 J10.2 JP1.3 Q5.5 Q5.6 Q5.7 Q5.8 Q5.9@2150,814.88 | length 3168.4
  Signal Layer 1 w9: J10.2@2345.24,511.38 2352.25,518.39 2352.25,699.42 2393.83,741 3751.59,741 3819.38,673.22 3953.38,673.22 3963.48,683.32 v4(3970.25,683.32)
  Bottom Layer w9: JP1.3@3900,1800 3970.25,1729.75 v4(3970.25,683.32)
  Bottom Layer w80: J10.2@2345.24,511.38 D3.1@2345.24,675.59
PTC: J7.2 R43.2 RT1.2 | length 2975.3
  Top Layer w9: R43.2@1909.14,1729.53 1914.35,1724.19 1915.7,1722.8 1918.33,1720.17 1964.69,1719.58 1980.1,1719.39 1985.32,1714.16 v1(1985.32,1684.82)
  Bottom Layer w9: J7.2@942.09,490.59 895,443.5 895,358.68 943.68,310 1347.12,310 1388.81,351.69 1416.44,351.69 1550,218.13 1983.13,218.13 2041.98,276.98 2041.98,698.02 1965,775 1965,1664.5 v1(1985.32,1684.82)
RT: R31.2 U1.12 | length 170.5
  Top Layer w9: U1.12@2608.9,2979.17 2608.9,2999.73 2614.17,3005 2659.15,3005 2685,3030.85 2685,3079.5 2690.5,3085 R31.2@2695,3085
SCL: J7.8 J8.9 JP11.1 R39.1 R42.2 U1.6 | length 7567.3
  Top Layer w9: U1.6@2654.17,2874.84 2754.84,2874.84 2792,2912 2799.5,2912 2805,2917.5 R42.2@2805,2925
  Top Layer w20: R42.2@2805,2925 v1(2830,2925)
  Bottom Layer w9: R39.1@1625,3285 1630.5,3290.5 1640.46,3290.5 1664.96,3315 2110,3315 2390,3035 2604.49,3035 2618.74,3020.75 2656.13,3020.75 2758.76,2918.13 2820.15,2918.13 2827.02,2925 v1(2830,2925) 2852.37,2902.63 2852.37,2811.49 2865.62,2798.25 3551.75,2798.25 JP11.1@3800,2550
  Bottom Layer w10: J7.8@1242.09,490.59 1192.68,540 1133.71,540 1107.63,566.09 1107.63,574.5 1107.37,574.75 1107.37,1044.94 234.25,1918.07 234.25,3073.82 633.44,3473.01 1541.13,3473.01 1595.35,3418.79 1595.35,3381.21 1560.52,3346.38 1560.52,3310.52 J8.9@1550,3300 1564.87,3300 1579.87,3285 R39.1@1625,3285
SDA: J7.6 J8.10 JP10.1 R40.1 R41.2 U1.5 | length 7872.1
  Top Layer w9: U1.5@2654.17,2855.16 2797.66,2855.16 2805,2862.5 R41.2@2805,2870
  Top Layer w20: R41.2@2805,2870 v1(2830,2870)
  Bottom Layer w9: J7.6@1142.09,490.59 1148.65,484.03 1186.89,484.03 1224,446.92 1260.18,446.92 1285.76,472.5 1285.76,509.24 1237.63,557.37 1141.87,557.37 1141.12,558.13 1140.16,558.13 1125,573.28 1125,1052.5 251.62,1925.88 251.62,3066.62 640,3455 1495,3455 J8.10@1550,3400 1501.25,3351.25 1501.25,3278.75 1530,3250 1650,3250 1672,3272 1672,3279.5 R40.1@1677.5,3285 ; R40.1@1685,3285 1692.5,3285 1705.63,3298.13 2103.01,3298.13 2386.14,3015 2600.63,3015 2611.75,3003.88 2649.14,3003.88 2751.77,2901.25 2798.75,2901.25 v1(2830,2870) 2830,2805 2853.63,2781.37 3543.63,2781.37 3725,2600 3725,2475 JP10.1@3800,2400
SS/ATRK: C37.1 TP13.1 U1.2 | length 2266.6
  Top Layer w9: U1.2@2654.17,2796.1 2713.9,2796.1 2792,2718 2799.5,2718 2805,2712.5 C37.1@2805,2705
  Top Layer w20: C37.1@2805,2705 2805,2672.72 v1(2805.45,2672.26)
  Bottom Layer w9: v1(2805.45,2672.26) 2807.56,2674.37 2815.34,2674.37 2818.73,2677.76 2948.88,2677.76 2998.2,2628.44 3546.25,2628.44 3612.07,2562.62 3612.07,1784.07 3896.14,1500 TP13.1@3900,1500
